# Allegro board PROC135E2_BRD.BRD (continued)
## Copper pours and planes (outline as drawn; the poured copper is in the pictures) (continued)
VCC_3V3_MAIN on TOP: 20.01,71.33 19.23,71.33 19.04,71.53 19.04,72.44 18.88,72.6 18.88,74.98 19.06,75.16 19.42,75.16 20.25,74.33 20.25,71.57
VCC_3V3_MAIN on TOP: 13.95,71.33 14.73,71.33 14.93,71.54 14.93,72.44 15.1,72.6 15.1,74.98 14.91,75.16 14.56,75.16 13.73,74.33 13.73,71.56
VCC_3V3_MAIN on BOTTOM: 20.31,87.96 20.31,85.21 19.06,85.21 19.06,88.04 19.25,88.23 20.04,88.23
VCC_3V3_MAIN on BOTTOM: 10.11,80.53 10.11,78.91 12.25,78.91 12.25,80.53
VCC_3V3_MAIN on BOTTOM: 14.32,76.38 16.13,76.38 16.45,76.06 16.45,74.41 16.29,74.26 15.76,74.26 15.55,74.46 15.55,75.09 15.26,75.39 14.32,75.39
VCC_3V3_MAIN on BOTTOM: 20.31,71.35 20.31,74.38 19.06,74.38 19.06,71.54 19.25,71.35
VCC_3V3_MAIN on BOTTOM: 20.5,84.62 21.52,84.62 22.13,84.01 22.13,79.09 22.4,78.82 22.4,77.3 21.94,76.85 20.53,76.85 20.53,80.63 20.35,80.81 20.35,81.47 20.5,81.62
VCC_3V3_MAIN on BOTTOM: 4.43,61.84 5.07,61.84 5.07,63.44 4.43,63.44
VCC_3V3_MAIN on BOTTOM: 13.66,71.59 13.66,74.38 14.91,74.38 14.91,71.54 14.72,71.35 13.9,71.35
VCC_3V3_MAIN on BOTTOM: 24.19,60.1 24.19,53.88 31.59,53.88 31.59,60.1
VCC_3V3_MAIN on BOTTOM: 13.66,88.23 13.66,85.23 14.91,85.23 14.91,88.04 14.72,88.23
VCC_3V3_MAIN on L06_PWR01: 0.87,88.91 16.94,88.91 16.94,101.45 19.12,103.63 20.18,103.63 21.65,102.16 21.65,101.65 19.26,99.25 19.26,91.91 22,89.17 22,81.29 25.2,78.09 43.69,78.09 43.69,53.47 2.63,53.47 0.87,55.23
VCC_3V3_SYS on TOP: 61.25,49.26 61.25,47.12 61.35,47.02 62.33,47.02 62.45,47.15 62.45,49.23 62.38,49.31 61.3,49.31
VCC_3V3_SYS on TOP: 9.51,134.5 13.53,134.5 13.53,135.77 11.85,135.77 11.53,135.45 9.51,135.45
VCC_3V3_SYS on TOP: 11.38,96.99 11.38,95.67 11.06,95.35 11.06,93.51 11.71,93.51 12.51,94.32 14.5,94.32 14.5,96.99
VCC_3V3_SYS on TOP: 54.86,123.35 55.66,123.35 55.66,122.9 55.98,122.58 57.31,122.58 57.49,122.39 57.49,122.13 57.34,121.97 55.1,121.97 54.86,122.22
VCC_3V3_SYS on TOP: 8.95,101.18 10.14,101.18 10.35,101.38 13.24,101.38 13.24,100.47 8.88,100.47 8.88,101.11
VCC_3V3_SYS on TOP: 9.51,153.09 13.64,153.09 13.64,151.85 11.81,151.85 11.53,152.13 9.51,152.13
VCC_3V3_SYS on TOP: 74.45,153.62 76.71,153.62 76.71,147.82 74.45,147.82
VCC_3V3_SYS on TOP: 47.23,54.89 47.23,58.39 51.74,58.39 51.74,54.89
VCC_3V3_SYS on BOTTOM: 76.46,150.15 77.54,150.15 77.67,150.03 77.67,149.41 77.77,149.31 80.41,149.31 80.46,149.26 80.46,147.33 80.03,146.89 76.62,146.89 76.46,147.06
VCC_3V3_SYS on BOTTOM: 71.22,87.67 71.22,86.07 72.65,86.07 72.65,87.67
VCC_3V3_SYS on BOTTOM: 13.24,63.01 13.24,59.14 15.57,59.14 15.57,63.01
VCC_3V3_SYS on BOTTOM: 16.61,136.41 18.34,136.41 18.47,136.28 18.47,135.5 17.35,134.38 16.79,134.38 16.61,134.56
VCC_3V3_SYS on BOTTOM: 66.65,44.84 66.65,42.61 67.85,42.61 67.85,44.84
VCC_3V3_SYS on BOTTOM: 8.03,110.94 10.67,110.94 10.67,109.71 11.75,109.71 12.59,110.55 12.9,110.55 13.05,110.7 13.05,113.06 13.25,113.26 13.71,113.26 13.81,113.16 13.81,110.57 13.43,110.19 12.79,110.19 11.63,109.02 11.63,107.94 14.3,107.94 14.3,106.77 10.06,106.77 9.1,107.74 9.1,109.46 8.26,110.3 8.03,110.3
VCC_3V3_SYS on BOTTOM: 54.9,122.65 54.9,122.02 57.5,122.02 57.5,122.65
VCC_3V3_SYS on BOTTOM: 58.69,78.76 58.69,77.29 59.66,77.29 59.66,78.76
VCC_3V3_SYS on BOTTOM: 64.83,132.78 65.29,132.78 65.29,132 66.21,132 66.21,131.76 65.58,131.13 65.1,131.13 64.78,131.45 64.78,132.73
VCC_3V3_SYS on BOTTOM: 64.62,84.77 64.62,80.65 63.12,80.65 63.12,83.91 62.13,83.91 62.13,84.7 63.4,84.7 63.47,84.77
VCC_3V3_SYS on L06_PWR01: 9.48,109.67 11.03,109.67 13.03,107.66 13.03,101.03 12.7,100.7 10.57,100.7 8.97,102.3 8.97,109.16
VCC_3V3_SYS on L08_PWR03: 0.64,154.54 84.36,154.54 84.36,5.71 0.64,5.71 ; 8 cut-outs
VCC_5V0 on BOTTOM (solid shape): 19.99,35.62 20.01,35.62 20.03,35.6 20.08,35.51 20.08,35.48 20.07,35.47 20.36,34.98 20.65,35.47 20.64,35.48 20.64,35.51 20.69,35.6 20.71,35.62 20.74,35.62 21.33,35.62 21.37,35.61 21.38,35.57 21.38,32.94 21.39,32.92 21.4,32.9 21.5,32.8 21.5,32.79 21.57,32.69 21.68,32.61 21.71,32.6 21.73,32.59 21.81,32.59 21.85,32.59 22.64,32.59 22.68,32.58 22.69,32.54 22.69,31.28 22.68,31.24 22.64,31.23 18.76,31.23 18.72,31.24 18.71,31.28 18.71,32.96 18.69,32.99 18.66,33.01 16.77,33.01 16.73,33.02 16.72,33.06 16.72,35.57 16.73,35.61 16.77,35.62
VCC_5V0 on TOP: 55.99,119.57 57.52,119.57 57.52,120.22 55.96,120.22 55.36,120.82 54.49,120.82 54.49,118.94 55.36,118.94
VCC_5V0 on TOP: 63.76,66.65 63.76,71.18 65.68,71.18 65.68,66.65
VCC_5V0 on BOTTOM: 7.01,138.24 8.21,138.24 8.21,137.07 7.44,137.07 7.37,137.15 6.5,137.15 6.5,137.71 6.89,137.71 7.01,137.83
VCC_5V0 on BOTTOM: 57.66,147.41 58.72,147.41 58.72,146.45 58.95,146.22 58.95,142.12 57.23,142.12 57.23,144.95 57.66,145.38
VCC_5V0 on BOTTOM: 0.76,116.37 0.76,117.44 3.69,117.44 3.69,116.98 1.98,116.98 1.98,116.37
VCC_5V0 on L06_PWR01: 48,19.55 59.28,30.83 59.28,32.73 68.13,41.58 68.13,71.13 67.41,71.84 51.23,71.84 51.23,62.88 48.47,60.11 48.47,52.67 47.5,51.7 47.5,45.53 45.98,44.01 45.98,38.44 37.42,29.88 22.29,29.88 21.61,30.57 21.61,34.81 20.69,35.72 11.97,35.72 11.97,19.55
VCC_5V0 on L06_PWR01: 7.56,145.75 58.12,145.75 59.38,144.49 59.38,127.12 57.51,125.25 57.51,121.96 58.35,121.12 60.7,121.12 61.19,120.63 61.19,117.01 60.76,116.57 50.76,116.57 50.76,135.09 6.62,135.09 6.02,134.49 5.08,134.49 4.63,134.95 4.63,142.81
VCC_5V0 on L07_PWR02: 0.64,139.08 9.22,139.08 10.87,137.43 10.87,112.99 0.64,112.99
VCC_5V0 on L08_PWR03: 54.92,121.15 65.84,121.15 69.95,117.03 69.95,67.48 68.81,66.33 64.29,66.33 63.81,66.82 63.81,72.35 64.23,72.77 64.23,83.86 63.81,84.28 63.81,89.93 64.23,90.35 64.23,112.9 61.97,115.16 54.92,115.16
VCC_CORE on TOP: 8.8,74.2 10.98,74.2 11.2,73.98 11.2,71.84 11.65,71.39 13.21,71.39 13.62,70.97 13.62,68.59 11.99,68.59 11.48,69.11 7.03,69.11 7.03,72.43
VCC_CORE on TOP: 15.22,94.29 18.66,94.29 19.02,93.93 19.4,93.93 19.41,93.94 21.52,93.94 23.39,92.07 24.05,92.07 24.72,91.4 24.72,85.23 22.77,85.23 22.77,88.15 22.51,88.41 20.47,88.41 20.07,88.81 20.07,90.55 19.56,91.07 14.37,91.07 14,90.69 14,89.02 13.39,88.41 11.75,88.41 11.26,87.92 11.26,85.28 9.61,85.28 9.61,90.96 12.55,93.89 14.82,93.89
VCC_CORE on BOTTOM: 13.57,68.54 13.57,70.96 12.7,71.83 9.61,71.83 9.03,71.25 9.03,69.92 10.41,68.54
VCC_CORE on BOTTOM: 12.55,93.01 16.83,93.01 17.25,93.43 21.47,93.43 22.08,92.82 22.08,91.17 21.77,90.87 21.77,88.53 20.17,88.53 19.92,88.79 19.92,90.54 19.39,91.07 14.2,91.07 14,90.86 14,89.04 13.28,88.33 9.81,88.33 9.81,91.43 10.84,92.46 12,92.46
VCC_CORE on L08_PWR03: 15.41,92.76 18.86,92.76 21.86,89.75 21.86,69.59 19.65,67.37 10.56,67.37 9.93,68 9.93,91.47 10.57,92.12 14.77,92.12
VCC_CSI_IO on TOP: 77.24,150.17 77.24,147.82 78.51,147.82 78.51,152.44 77.24,152.44 77.13,152.33 77.13,150.28
VCC_CSI_IO on BOTTOM: 57.98,152.1 57.98,150.58 61.47,150.58 61.47,152.1
VCC_CSI_IO on L07_PWR02: 50.73,143.19 50.42,143.5 50.42,154.16 78.06,154.16 78.06,143.19
VDD1_LPDDR4_1V8 on BOTTOM: 29.82,79.11 31.35,79.11 31.35,80.52 29.82,80.52
VDD1_LPDDR4_1V8 on L07_PWR02: 47.7,90.54 47.7,76.75 29.84,76.75 29.84,87.21 33.17,90.54
VDD_1V0 on TOP: 54.86,112.4 55.66,112.4 55.66,112.85 55.98,113.17 57.31,113.17 57.49,113.36 57.49,113.62 57.34,113.78 55.1,113.78 54.86,113.53
VDD_1V0 on BOTTOM: 70.08,107.61 70.08,106.13 69.91,105.96 69.45,105.96 69.04,106.36 65.84,106.36 65.84,107.61
VDD_1V0 on BOTTOM: 54.89,113.67 54.89,112.84 57.52,112.84 57.52,113.67
VDD_1V0 on L06_PWR01: 54.66,115.63 61.22,115.63 67.16,109.69 67.16,106.01 66.19,105.04 66.19,100.98 64.37,99.15 64.37,96.48 65.51,95.34 65.51,94.96 64.65,94.1 58.78,94.1 58.78,108.42 54.66,112.54
VDD_1V0 on L07_PWR02: 59.39,99.73 60.73,99.73 60.97,99.49 60.97,94.29 57.4,90.72 56.44,90.72 56.27,90.88 56.27,96.62
VDD_1V2 on BOTTOM: 12.9,123.97 12.9,119.81 14.7,119.81 14.7,123.97
VDD_1V2 on L07_PWR02: 12.62,125.04 23.58,125.04 30.42,118.2 53.49,118.2 60.5,111.2 60.5,110.18 63.3,107.38 63.3,103.98 62.38,103.06 53.39,103.06 52.56,103.9 52.56,106.06 45.72,112.89 14.58,112.89 11.64,115.83 11.64,124.06
VDD_2V5 on TOP: 64.54,97.05 65.92,97.05 65.98,97 65.98,96.41 65.88,96.31 65.21,96.31 65.07,96.17 65.07,94.33 65.24,94.16 65.81,94.16 65.9,94.07 65.9,93.48 65.79,93.38 65.04,93.38 64.54,93.88
VDD_2V5 on TOP: 60.88,123.35 60.08,123.35 60.08,122.9 59.75,122.58 58.43,122.58 58.24,122.4 58.24,122.16 58.43,121.97 60.63,121.97 60.88,122.22
VDD_2V5 on BOTTOM: 58.25,122.55 58.25,121.82 60.85,121.82 60.85,122.55
VDD_2V5 on BOTTOM: 67.11,86.25 65.33,86.25 65.33,87.03 63.83,87.03 63.83,88.25 64.52,88.94 66.27,88.94 67.11,88.1
VDD_2V5 on L06_PWR01: 59.59,126.43 62.87,126.43 73.1,116.19 73.1,101.59 74.09,100.6 74.09,89.27 69.04,84.21 60.15,84.21 58.93,85.43 58.93,88.99 60.76,90.82 62.13,90.82 66.22,94.91 66.22,95.54 65.36,96.41 65.2,96.41 65,96.61 65,98.9 66.91,100.8 66.91,104.74 67.92,105.75 67.92,113.29 62.89,118.32 62.89,120.77 61.93,121.73 58.73,121.73 58.24,122.21 58.24,125.08
VDD_CORE on TOP: 52.81,106.55 54.28,106.55 55.02,105.8 55.02,101.55 53.82,101.55 53.82,105.1 53.44,105.47 52.81,105.47
VDD_CORE on TOP: 15.12,100.3 15.12,94.71 20.3,94.71 20.3,100.3
VDD_CORE on BOTTOM: 23.35,97.09 24.95,97.09 24.95,95.89 21.37,95.89 20.7,96.56 19.02,96.56 18.47,96.01 15.38,96.01 15.38,98.22 15.67,98.51 16.3,98.51 16.63,98.85 16.63,99.99 16.96,100.31 19.36,100.31 20.85,98.82 20.85,98.36 21.99,97.23 23.21,97.23
VDD_CORE on L08_PWR03: 23.8,122.11 53.88,122.11 53.88,117.73 54.37,117.23 54.37,103.99 53.75,103.37 48.24,103.37 47.22,102.35 44.3,102.35 42.99,101.04 37.47,101.04 37.17,100.75 29.9,100.75 28.56,99.4 28.56,95.12 15.26,95.12 11.94,98.44 11.94,110.26
VDD_CORE_REG_SW1 on TOP: 11.64,87.59 13.26,87.59 13.26,85.28 14.38,84.16 14.38,83.45 14.33,83.4 13.21,83.4 11.64,84.98
VDD_CORE_REG_SW2 on TOP: 22.34,87.59 20.71,87.59 20.71,85.28 19.6,84.16 19.6,83.45 19.65,83.4 20.76,83.4 22.34,84.98
VDD_CORE_REG_SW3 on TOP: 11.64,71.99 13.26,71.99 13.26,74.3 14.38,75.42 14.38,76.13 14.33,76.18 13.21,76.18 11.64,74.61
VDD_LPDDR4 on TOP: 28.23,73.52 28.23,69.54 34.49,69.54 34.49,76.47 34.67,76.65 48.51,76.65 50.83,78.96 50.83,90.62 51.77,91.56 51.77,94.15 49.87,96.05 47.53,96.05 46.84,95.37 46.84,94.31 45.4,92.88 34.06,92.88 30.81,96.13 28.24,96.13 27.05,94.95 27.05,80.07 28.93,78.19 28.93,73.52 ; 9 cut-outs
VDD_LPDDR4 on L08_PWR03: 29.62,76.25 52.02,76.25 52.02,96.21 47.65,100.58 37.62,100.58 37.28,100.23 36.66,100.23 35.8,99.37 35.8,98.18 35.39,97.77 29.82,97.77 29.82,92.8 28.58,91.56 28.58,77.29
VDD_MMC1 on TOP: 5.94,99.23 5.94,100.22 6.29,100.57 7.28,100.57 7.28,101.35 4.57,101.35 4.57,99.23
VDD_MMC1_SD on TOP: 3.75,96.96 3.75,98.87 6.21,98.87 6.21,96.96
VDD_MMC1_SD on BOTTOM: 3.84,97.86 5.59,97.86 5.81,98.08 6.18,98.08 6.18,96.94 5.75,96.94 5.63,97.06 3.84,97.06
VDDA1V8 on TOP: 22.63,79.2 23.99,79.2 24.03,79.16 24.03,78.06 22.53,78.06 22.5,78.09 22.5,79.06
VDDA1V8 on TOP: 44.66,73.65 44.66,70.96 42.78,70.96 42.78,73.65
VDDA1V8 on BOTTOM: 42.62,73.47 42.62,71.36 43.56,71.36 43.56,73.47
VDDA1V8 on L08_PWR03: 22.49,79.03 23.93,79.03 24.74,78.22 24.74,75.48 26.67,73.55 43.74,73.55 43.74,70.73 25.45,70.73 22.49,73.69
VDDA_1V8 on TOP: 45.11,73.65 45.11,70.96 46.71,70.96 48.62,72.86 48.62,75.91 47.09,75.91 47.09,74.16 46.59,73.65
VDDA_1V8 on TOP: 60.62,134.14 60.62,132.77 61.71,132.77 61.71,134.14
VDDA_1V8 on BOTTOM: 53.01,100.31 53.01,98.76 54.18,98.76 54.18,100.31
VDDA_1V8 on BOTTOM: 52.01,106.53 51.68,106.86 51.68,112.48 52.88,113.67 52.88,124.9 52.9,124.87 55.14,127.11 57.63,127.11 58.62,128.1 58.62,128.53 58.74,128.66 58.74,131.7 58.72,131.73 59.54,132.55 60.51,132.55 60.88,132.92 60.88,133.23 61.05,133.41 61.87,133.41 61.87,132.54 60.93,131.6 60.52,131.6 59.53,130.61 59.53,126.52 58.84,125.84 57.35,125.84 54.63,123.12 54.63,112.81 55.03,112.4 55.03,107.65 53.92,106.53
VDDA_1V8 on L05_SIG02: 38.23,102.55 38.23,101.56 43.92,101.56 43.92,102.55
VDDA_1V8 on L06_PWR01: 46.46,72.94 46.46,77.6 50.78,81.92 50.78,95.36 45.66,100.48 43.28,100.48 43.28,105.35 41.68,106.95 37.51,106.95 35.28,109.18 35.28,110.73 36,111.45 54.78,111.45 58.16,108.07 58.16,72.94
VDDA_1V8_FB1 on TOP: 51.44,100.34 51.44,98.97 52.63,98.97 52.63,100.34
VDDA_1V8_FB1 on BOTTOM: 51.44,100.39 51.44,98.9 52.61,98.9 52.61,100.39
VDDA_1V8_FB1 on L03_SIG01: 38.01,105.71 40.54,105.71 42.14,104.1 50.74,104.1 51.54,103.3 52.55,103.3 53.09,102.76 53.09,99.26 52.64,98.82 51.48,98.82 49.07,101.22 47.37,101.22 46.93,100.78 38.1,100.78 37.59,101.28 36.63,101.28 36.63,102.26 36.93,102.56 37.28,102.56 37.35,102.64 37.35,105.05
VDDA_1V8_FB2 on BOTTOM: 50.45,106.44 50.71,106.44 50.94,106.21 52.71,106.21 52.71,105.56 50.69,105.56 50.33,105.92 50.33,106.33
VDDA_1V8_FB2 on L07_PWR02: 47.99,106.48 50.74,106.48 51.14,106.08 51.14,104.89 50.25,104 44.73,104 44.73,104.14 45.19,104.6 45.19,105.46 45.47,105.74 47.25,105.74
VDDA_CORE_CSI on TOP: 51.63,104.51 51.63,103.51 53.28,103.51 53.28,104.51
VDDA_CORE_CSI on L07_PWR02: 44.48,103.36 50.53,103.36 51.45,104.27 51.96,104.27 52.14,104.09 52.14,103.09 51.4,102.35 44.87,102.35 44.42,102.8 44.42,103.3
VDDA_CORE_USB on TOP: 51.63,102.58 51.63,101.54 53.32,101.54 53.32,102.58
VDDA_CORE_USB on L08_PWR03: 47.98,102.08 48.54,102.64 52.53,102.64 52.53,100.19 48.64,100.19 47.98,100.85
VDDA_DDR_PLL0 on BOTTOM: 24.46,99.25 25.45,99.25 25.45,98.69 25.94,98.21 25.94,97.6 23.98,97.6 23.88,97.7 23.88,98.67
VDDA_DDR_PLL0 on L07_PWR02: 29.71,99.35 29.71,98.39 37.73,98.39 37.96,98.62 37.96,99.35
VDDA_LM5141 on BOTTOM: 30.43,44.93 31.74,44.93 31.81,45 32.69,45 32.69,44.22 31.07,44.22 31.07,43.76 30.96,43.66 30.57,43.66 30.43,43.8
VDDA_LM5141 on L07_PWR02: 30.43,46.78 30.43,42.62 36.12,42.62 36.12,46.78
VDDC_1V2 on L07_PWR02: 50.43,14.5 50.68,14.26 53.16,14.26 53.16,17.29 56.39,20.51 59.82,20.51 59.82,23.17 55.17,23.17 50.43,18.44
VDDR_CORE on TOP: 23.33,95.27 23.33,93.96 23.17,93.8 22.67,93.8 22.67,93.31 23.57,92.41 24.77,92.41 24.77,95.27
VDDR_CORE on BOTTOM: 22.53,94.41 22.53,91.1 22.1,90.67 22.1,88.66 24.87,88.66 24.87,94.41
VDDR_CORE on L06_PWR01: 37.32,106.49 41.42,106.49 42.78,105.14 42.78,100.38 36.98,100.38 35.72,101.63 29.23,101.63 28.86,101.26 26.84,101.26 23.88,98.3 23.88,93.13 23.29,92.55 19.94,92.55 19.94,99.05 26.64,105.75 36.58,105.75
(no net) on TOP: 19.85,33.11 20.93,33.11 21.82,32.22 22.85,32.22 22.85,31.28 22.56,31 17.4,31 17.4,35.66 19.95,35.66 20.61,35 20.61,34.38 20.49,34.25 19.95,34.25 19.85,34.15
(no net) on TOP: 14.48,49.41 16.36,49.41 16.36,47.59 15.54,47.59 15.03,48.11 14.48,48.11
(no net) on TOP: 8.31,43.61 7.43,43.61 7.35,43.68 7.35,43.98 7.24,44.09 6.92,44.09 6.83,44 6.83,43.85 5.91,43.85 5.91,43.55 6.83,43.55 6.83,43.28 6.93,43.18 7.23,43.18 7.34,43.29 8.31,43.29
(no net) on TOP: 5.87,31.36 6.77,31.36 6.83,31.41 6.83,31.81 6.97,31.96 7.21,31.96 7.35,31.81 7.35,31.6 8.27,31.6 8.27,31.3 7.35,31.3 7.35,31.16 7.23,31.04 5.87,31.04
(no net) on TOP: 24.15,32.32 24.15,26.49 26.04,26.49 26.04,29.93 24.8,31.17 24.8,32.32
(no net) on TOP: 21.85,29.93 21.85,26.48 23.75,26.48 23.75,32.32 23.12,32.32 23.12,31.2
(no net) on TOP: 5.87,46.36 6.75,46.36 6.83,46.43 6.83,46.73 6.94,46.84 7.26,46.84 7.35,46.75 7.35,46.6 8.27,46.6 8.27,46.3 7.35,46.3 7.35,46.03 7.25,45.93 6.95,45.93 6.84,46.04 5.87,46.04
(no net) on TOP: 13.64,43.89 16.24,43.89 16.24,42.97 13.64,42.97
(no net) on TOP: 14.01,42.67 16.35,42.67 16.35,40.38 15.56,40.38 15.14,39.96 14.01,39.96
(no net) on TOP: 8.31,28.61 7.43,28.61 7.35,28.68 7.35,28.98 7.24,29.09 6.92,29.09 6.83,29 6.83,28.85 5.91,28.85 5.91,28.55 6.83,28.55 6.83,28.28 6.93,28.18 7.23,28.18 7.34,28.29 8.31,28.29
(no net) on TOP: 24.98,32.23 24.98,31.53 26.2,30.31 29.99,30.31 29.99,33.72 27.9,33.72 27.9,32.3 26.12,32.3 26.04,32.23
(no net) on BOTTOM: 16.26,50.18 16.26,49.36 16.59,49.02 16.59,48.79 16.96,48.42 17.36,48.42 17.36,47.23 16.56,47.23 16.25,47.54 14.57,47.54 14.57,48.27 14.25,48.59 14.25,50.04 14.39,50.18
(no net) on BOTTOM: 16.48,43.23 17.39,43.23 17.39,43.95 14.47,43.95 14.06,43.55 14.06,41.08 15.08,41.08 15.08,42.66 15.38,42.96 16.2,42.96
(no net) on BOTTOM: 16.96,49.39 17.62,49.39 17.9,49.11 17.9,48.14 18.02,48.02 19.22,48.02 19.22,48.85 19.5,48.85 19.5,45.37 17.77,45.37 17.62,45.53 17.62,47.94 17.51,48.04 17.51,48.55 17.44,48.63 16.96,48.63
(no net) on BOTTOM: 63.56,104.68 65.08,104.68 65.34,104.42 65.34,103.99 65.21,103.86 62.63,103.86 62.31,104.18 62.31,105.27 63.4,105.27 63.4,104.84
(no net) on BOTTOM: 5.11,46.74 9.04,46.74 9.04,46.05 8.56,46.05 8.56,43.7 8.94,43.7 8.94,43.03 5.11,43.03
(no net) on BOTTOM: 26.58,33.69 26.58,30.32 29.95,30.32 29.95,33.69
(no net) on BOTTOM: 16.59,43.08 17.41,43.08 17.41,42.38 17.14,42.11 16.9,42.11 16.37,41.57 16.37,40.98 16.24,40.86 15.5,40.86 15.39,40.96 15.39,42.53 15.56,42.7 16.21,42.7
(no net) on BOTTOM: 67.36,103.37 67.31,103.42 67.31,103.86 67.21,103.96 66,103.96 65.83,104.14 65.83,104.42 66,104.59 68.16,104.59 68.53,104.96 69.43,104.96 69.43,105.26 69.61,105.44 69.89,105.44 70.06,105.26 70.06,103.37
(no net) on BOTTOM: 16.96,40.95 17.62,40.95 17.95,41.28 17.95,42.32 19.17,42.32 19.22,42.28 19.22,41.44 19.5,41.44 19.5,44.96 17.77,44.96 17.62,44.81 17.62,42.23 17.51,42.13 17.51,41.79 17.44,41.71 16.96,41.71
(no net) on BOTTOM: 11.48,29.63 11.19,29.92 11.19,32.82 11.55,33.18 12.12,33.18 13.65,34.71 13.65,38.57 15.08,40 15.08,43.08 14.61,43.55 14.06,43.55 14.06,40.84 11.83,38.61 11.83,35.99 11.14,35.29 9.42,35.29 8.96,34.83 8.96,33.86 8.26,33.16 5.2,33.16 5.2,28.05 6.33,26.92 11.52,26.92 12,26.45 17.19,26.45 17.5,26.76 17.5,29.38 15.33,29.38 15.07,29.63
(no net) on BOTTOM: outline of 97 points within 0.63,5.71 84.36,154.54 ; 85 cut-outs
(no net) on BOTTOM: 22.69,32.59 22.69,31.23 18.71,31.23 18.71,33.01 16.72,33.01 16.72,35.62 21.38,35.62 21.38,32.92 21.71,32.59
(no net) on L03_SIG01: outline of 96 points within 0.63,5.71 84.36,154.54 ; 116 cut-outs
(no net) on L05_SIG02: outline of 96 points within 0.63,5.71 84.36,154.54 ; 214 cut-outs
(no net) on L07_PWR02: 18.54,47 15.69,47 15,46.3 15,45.16 12.12,42.29 4.67,42.29 4.67,48 8.08,48 9.38,49.29 9.38,52.02 10.4,53.04 17.99,53.04 18.54,52.48
(no net) on L10_SIG03: outline of 96 points within 0.63,5.71 84.36,154.54 ; 177 cut-outs
CAN_IO_3V3 on BOTTOM: 4.43,66.21 5.07,66.21 5.07,63.82 4.43,63.82
CAN_IO_3V3 on L07_PWR02: 0.94,67.2 4.01,67.2 4.01,67.16 19.83,67.16 21.08,65.91 21.08,61.41 23.85,58.64 25.22,58.64 29.7,54.17 29.7,41.71 31.63,39.78 31.63,25.54 33.89,23.28 33.89,18 32.9,17.01 26.19,17.01 26.19,18.68 28.78,18.68 30.01,19.91 30.01,23.34 26.6,26.76 26.6,51.27 23.52,54.34 0.94,54.34
CPSW1_GPIO_0 on BOTTOM: 81.95,84.9 81.95,82.3 82.43,82.3 82.43,81.47 83.22,81.47 83.22,84.9
CPSW1_LED_1000 on BOTTOM: 82.38,106.99 82.38,104.42 83.65,104.42 83.65,106.99
CPSW1_LED_ACT on BOTTOM: 79.29,84.93 79.29,82.32 79.76,82.32 79.76,81.49 80.56,81.49 80.56,84.93
CS_LM5141 on BOTTOM: 32.23,58.04 32.23,53.86 42.98,53.86 42.98,58.68 34.44,58.68 33.8,58.04
DRAIN1 on BOTTOM (solid shape): 17.59,49.39 17.61,49.38 17.63,49.37 17.88,49.12 17.89,49.11 17.9,49.09 17.9,48.16 17.9,48.14 17.92,48.11 17.93,48.09 17.93,48.05 17.94,48.01 17.98,48 19.18,48 19.22,48.01 19.23,48.05 19.23,48.4 19.25,48.46 19.25,48.51 19.25,48.8 19.27,48.84 19.3,48.85 19.44,48.85 19.47,48.84 19.49,48.8 19.49,48.59 19.48,48.55 19.47,48.51 19.47,47.85 19.48,47.79 19.5,47.74 19.5,45.43 19.48,45.39 19.44,45.37 17.79,45.37 17.77,45.38 17.75,45.39 17.63,45.51 17.62,45.53 17.62,45.55 17.62,47.92 17.61,47.94 17.59,47.98 17.59,48.04 17.57,48.07 17.57,48.08 17.57,48.58 17.55,48.61 17.51,48.63 17.07,48.63 17.05,48.63 17.03,48.64 16.97,48.7 16.96,48.72 16.96,48.74 16.96,49.34 16.97,49.37 17.01,49.39
DRAIN1 on L08_PWR03: 17.57,47.95 17.57,45.48 19.38,45.48 19.38,47.95
DRAIN2 on BOTTOM (solid shape): 19.44,44.96 19.48,44.95 19.5,44.91 19.5,42.63 19.49,42.61 19.47,42.59 19.47,41.81 19.48,41.76 19.49,41.72 19.49,41.49 19.47,41.45 19.44,41.44 19.29,41.44 19.25,41.45 19.23,41.49 19.23,42.26 19.22,42.3 19.17,42.32 17.95,42.32 17.95,42.31 17.93,42.29 17.93,41.28 17.92,41.26 17.91,41.24 17.63,40.96 17.61,40.95 17.59,40.95 17.01,40.95 16.97,40.96 16.96,41 16.96,41.66 16.97,41.69 17.01,41.71 17.42,41.71 17.44,41.71 17.45,41.72 17.5,41.77 17.51,41.79 17.51,41.81 17.51,42.1 17.52,42.12 17.53,42.14 17.6,42.21 17.61,42.23 17.62,42.25 17.62,42.3 17.62,43.28 17.62,43.28 17.62,44.79 17.62,44.81 17.63,44.82 17.75,44.95 17.77,44.96 17.79,44.96
DRAIN2 on L08_PWR03: 17.57,44.85 17.57,42.44 19.38,42.44 19.38,44.85
ETH1_EARTH on TOP: 74.91,100.93 74.91,88.23 74.27,87.59 74.27,83.15 77.15,83.15 77.15,85.4 84.29,85.4 84.29,103.95 74.27,103.95 74.27,101.56
ETH1_EARTH on BOTTOM: 74.91,100.93 74.91,88.23 74.27,87.59 74.27,83.15 77.15,83.15 77.15,85.4 84.29,85.4 84.29,103.95 74.27,103.95 74.27,101.56 ; 2 cut-outs
ETH1_EARTH on L02_GND01, L03_SIG01, L04_GND02, L05_SIG02, L06_PWR01, L07_PWR02, L08_PWR03, L09_GND03, L10_SIG03, L11_GND04: 74.91,100.93 74.91,88.23 74.27,87.59 74.27,83.15 77.15,83.15 77.15,85.4 84.29,85.4 84.29,103.95 74.27,103.95 74.27,101.56
FT4232_USB_VBUS on TOP: 9.28,17.84 4.97,17.84 4.97,18.53 5.69,19.25 9.28,19.25
FT4232_USB_VBUS on BOTTOM: 9.23,11.44 9.74,11.44 9.74,10.55 9.76,10.54 9.76,8.99 9.72,8.95 7.94,8.95 7.71,9.18 7.71,13.85 7.41,14.16 7.41,17.36 7,17.76 7,18.49 7.7,19.19 9.26,19.19 9.61,18.83 9.61,17.92 9.23,17.54
HDMI_EARTH on TOP: 0.64,125.13 7.75,125.13 8.44,124.45 8.44,122.95 7.72,122.24 4.22,122.24 3.18,121.2 3.18,110.83 4.35,109.67 7.95,109.67 8.41,109.21 8.41,107.43 7.77,106.8 3.36,106.8 3.15,106.59 3.15,105.75 2.95,105.55 0.89,105.55 0.64,105.8
HDMI_EARTH on L02_GND01: 0.64,125.13 7.75,125.13 8.44,124.45 8.44,122.95 7.72,122.24 4.22,122.24 3.18,121.2 3.18,110.83 4.35,109.67 7.95,109.67 8.41,109.21 8.41,107.43 7.77,106.8 3.36,106.8 3.15,106.59 3.15,105.75 2.95,105.55 0.89,105.55 0.64,105.81
LDO_3V3 on L07_PWR02: 20.04,51.49 25.04,51.49 26,50.53 26,48.16 22.67,44.83 15.64,44.83 15.64,46.33 18.53,46.33 19.63,47.43 19.63,51.08
SOC_DVDD1V8 on TOP: 2.99,89.19 5.73,89.19 5.73,86.5 2.71,86.5 2.71,88.91
SOC_DVDD1V8 on BOTTOM: 28.12,78.7 31.45,78.7 31.45,76.98 28.12,76.98
SOC_DVDD1V8 on L07_PWR02: 0.65,109.55 3.3,112.21 39.22,112.21 39.22,107.51 38.43,107.51 38.1,107.18 38.1,106.82 37.95,106.67 37.7,106.67 37.21,107.15 35.74,107.15 34.88,106.29 34.88,104.37 14.7,104.37 11.6,101.27 11.6,94.22 39.02,94.22 43.03,98.24 43.03,100.32 43.61,100.9 44.76,100.9 44.76,99.89 45.65,98.99 45.65,94.96 41.87,91.17 32.84,91.17 29.09,87.42 27.97,87.42 27.7,87.14 27.7,83.29 28.87,82.11 28.87,75.71 24.37,75.71 23.01,77.07 23.01,81.06 22.1,81.97 11.62,81.97 8.64,84.95 4.6,84.95 0.65,88.9
SOC_DVDD3V3 on TOP: 11.82,100.16 11.82,97.5 14.66,97.5 14.66,100.16
SOC_DVDD3V3 on L07_PWR02: 35.49,106.31 37.34,106.31 37.47,106.19 37.98,106.19 38.43,106.64 38.43,106.85 38.59,107 39.56,107 40.08,107.52 44.29,107.52 44.76,107.05 44.76,105.38 43.55,104.16 43.55,103.12 44.51,102.15 44.51,101.51 43.63,101.51 42.39,100.27 42.39,98.69 38.89,95.19 12.11,95.19 12.11,101.19 14.59,103.68 35.31,103.68 35.31,106.13
SOC_USB0_VBUS on L07_PWR02: 51.01,76.54 51.01,88.89 53.49,91.38 53.49,97.14 49.25,101.39 48.01,101.39 47.73,101.11 47.73,99.84 51.21,96.36 51.21,91.43 48.97,89.19 48.97,76.54
SOC_VDDSHV5_SDIO on L06_PWR01: 34.92,108.93 23.32,108.93 22.71,108.32 22.71,106.72 23.04,106.39 36.27,106.39 36.5,106.62 36.5,107.35
SW_LM5141 on TOP: 45.49,53.45 45.49,44.66 40.87,44.66 40.87,51.14 42.15,51.14 42.15,53.45
SW_LM5141 on BOTTOM: 35.36,53.44 35.36,49.75 35.17,49.56 35.17,48.67 35.46,48.38 36.21,48.38 36.72,48.89 40.66,48.89 40.66,47.19 45.5,47.19 45.5,53.44
UART_SHIELD on TOP, BOTTOM, L02_GND01, L03_SIG01, L04_GND02, L05_SIG02, L06_PWR01, L07_PWR02, L08_PWR03, L09_GND03, L10_SIG03, L11_GND04: 0.64,23.32 6.83,23.32 6.83,20.18 6.53,19.88 4.07,19.88 3.65,19.45 3.65,14.15 4.16,13.63 6.48,13.63 6.86,13.25 6.86,11.66 0.64,11.66
USB_TYPEA_EARTH on TOP, BOTTOM, L02_GND01, L03_SIG01, L04_GND02, L05_SIG02, L06_PWR01, L07_PWR02, L08_PWR03, L09_GND03, L10_SIG03, L11_GND04: 72.62,79.66 72.62,77.31 76.81,77.31 77.61,76.51 77.61,68.02 76.86,67.27 72.62,67.27 72.62,64.99 84.36,64.99 84.36,79.66
USB_TYPEC1_EARTH on TOP, BOTTOM, L02_GND01, L03_SIG01, L04_GND02, L05_SIG02, L06_PWR01, L07_PWR02, L08_PWR03, L09_GND03, L10_SIG03, L11_GND04: 0.64,39.11 0.64,52.35 8.23,52.35 8.23,49.05 7.98,48.79 4.27,48.79 3.77,48.29 3.77,41.58 4.23,41.13 7.94,41.13 8.23,40.83 8.23,39.11
USB_TYPEC2_EARTH on TOP, BOTTOM, L02_GND01, L03_SIG01, L04_GND02, L05_SIG02, L06_PWR01, L07_PWR02, L08_PWR03, L09_GND03, L10_SIG03, L11_GND04: 0.64,24.11 0.64,37.35 8.23,37.35 8.23,34.05 7.98,33.79 4.27,33.79 3.77,33.29 3.77,26.58 4.23,26.13 7.94,26.13 8.23,25.83 8.23,24.11
VHDMI_AVCC_1V2 on BOTTOM: 13.24,119.11 15.36,119.11 15.36,115.53 14.53,115.53 14.15,115.91 14.15,117.16 13.24,118.07
VHDMI_CVCC_1V2 on BOTTOM: 15.46,124.05 15.46,122.55 17.04,122.55 17.04,124.05
VHDMI_CVCC_1V2 on L06_PWR01: 16.59,123.94 18.21,123.94 19.85,122.3 19.85,120.73 20.14,120.44 21.64,120.44 22.02,120.82 22.02,122.21 23.95,122.21 25.05,121.12 25.05,112.89 23.14,110.98 18.24,110.98 17.99,111.24 17.99,116.02 16.36,117.64 16.36,123.71
VHDMI_IOVCC_3V3 on BOTTOM: 13.19,110.04 13.19,108.55 14.71,108.55 14.71,110.04
VHDMI_IOVCC_3V3 on L06_PWR01: 14.28,126.38 24.59,126.38 28.3,122.67 28.3,114.19 27.33,113.22 25.71,113.22 25.71,121.65 24.69,122.67 21.06,122.67 21.06,121.07 20.88,120.89 20.63,120.89 20.5,121.02 20.5,122.34 18.44,124.4 16.23,124.4 15.32,123.48 15.32,117.87 17.43,115.76 17.43,109.56 12.63,109.56 12.14,110.05 12.14,124.25
VMAIN on BOTTOM (solid shape): 29.9,33.69 29.93,33.68 29.94,33.66 29.95,33.63 29.95,30.37 29.94,30.34 29.93,30.33 29.9,30.32 26.63,30.32 26.6,30.33 26.59,30.34 26.58,30.37 26.58,33.21 27.21,33.21 27.21,33.16 27.21,33.11 27.23,33.06 27.25,33.01 27.28,32.97 27.32,32.93 27.36,32.9 27.41,32.88 27.46,32.86 27.51,32.86 27.56,32.86 27.61,32.86 27.66,32.88 27.71,32.9 27.75,32.93 27.79,32.97 27.82,33.01 27.84,33.06 27.86,33.11 27.87,33.16 27.87,33.21 27.86,33.26 27.84,33.31 27.82,33.36 27.79,33.4 27.75,33.44 27.71,33.47 27.66,33.49 27.61,33.51 27.56,33.52 27.51,33.52 27.46,33.51 27.41,33.49 27.36,33.47 27.32,33.44 27.28,33.4 27.25,33.36 27.23,33.31 27.21,33.26 27.21,33.21 26.58,33.21 26.58,33.63 26.59,33.66 26.6,33.68 26.63,33.69
VMAIN on TOP: 13.84,47.76 14.86,47.76 15.32,47.29 16.27,47.29 16.39,47.17 16.39,46.6 16.19,46.4 14.96,46.4 14.81,46.55 13.84,46.55
VMAIN on TOP: 32.01,40.12 32.01,52.39 40.46,52.39 40.46,40.12
VMAIN on BOTTOM: 46.11,10.63 46.47,10.63 46.47,9.66 46.85,9.28 46.85,7.33 46.55,7.02 44.49,7.02 44.49,7.96 45.81,7.96 45.81,9.36 46.11,9.66
VMAIN on BOTTOM: 14.95,47.33 14.95,46.39 17.36,46.39 17.36,47.08 16.43,47.08 16.18,47.33
VMAIN on L06_PWR01: 9.35,52.52 9.35,36.69 21.4,36.69 22.9,35.19 22.9,31.03 33.52,31.03 36.3,33.81 39.43,33.81 41.74,36.12 41.74,52.52
VMAIN on L08_PWR03: 44.21,6.1 43.31,7 43.31,10.25 42.01,11.55 27.1,11.55 24.06,14.59 24.06,34.7 29.15,34.7 30.38,33.47 30.38,26.89 29.44,25.95 29.44,17.87 32.41,14.9 46.64,14.9 47.75,13.78 47.75,6.72 47.13,6.1
VPP_1V8 on TOP: 22.8,82.61 24.09,82.61 24.09,81.45 23.97,81.32 21.9,81.32 21.9,81.71
VPP_1V8 on L06_PWR01: 25.61,95.13 25.61,90.64 25.35,90.39 25.35,82.79 24.21,81.65 22.49,81.65 22.49,82.47 23.12,83.1 23.12,91.5 24.39,92.77 24.39,97.97 27.18,100.76 29.22,100.76 29.22,99.33 27.66,99.33 26.26,97.93 26.26,95.79
VPP_1V8 on L08_PWR03: 29.03,99.9 35.13,99.9 35.28,99.76 35.28,98.62 35.01,98.35 29.11,98.35 28.76,98.71 28.76,99.64
XDS_SHIELD on TOP, BOTTOM, L02_GND01, L03_SIG01, L04_GND02, L05_SIG02, L06_PWR01, L07_PWR02, L08_PWR03, L09_GND03, L10_SIG03, L11_GND04: 77.07,12.23 77.07,9.87 78.27,9.87 80,11.59 84.36,11.59 84.36,22.57 78.08,22.57 78.08,19.77 80.27,19.77 81.09,18.96 81.09,13.95 80.89,13.75 78.59,13.75
XDS_USB_VBUS on TOP: 75.29,15.69 79.99,15.69 79.99,15.03 79.35,14.39 76.37,14.39 76.06,14.08 75.29,14.08
XDS_USB_VBUS on BOTTOM: 73.84,17.44 73.84,24.09 75.22,24.09 75.22,22.76 75.44,22.76 75.44,21.27 78.73,17.99 78.73,14.78 78,14.05 74.78,14.05 74.78,16.5
XDS_USB_VBUS on L08_PWR03: 57.16,26.65 57.16,25.59 58.33,24.42 73.19,24.42 73.7,23.91 73.7,10.17 72.65,9.12 48.72,9.12 48.72,6.21 76.25,6.21 78.03,7.99 78.03,21.08 79.92,22.97 79.92,26.2 79.46,26.65
N17133547 on BOTTOM: 71.22,90.82 71.22,88.05 72.75,88.05 72.75,90.82
N17153383 on TOP: 25.05,89.32 26.27,89.32 26.27,85.84 25.05,85.84
N17153383 on BOTTOM: 22.1,88.25 24.77,88.25 24.77,86.93 25.61,86.93 25.61,85.99 25.43,85.81 25.2,85.81 24.67,85.28 23.6,85.28 23.6,86.37 23.19,86.78 22.1,86.78
N17253632 on TOP: 48.23,15.52 48.23,11.92 51.12,11.92 51.12,13.62 50.39,14.36 50.39,15.52
N17253632 on BOTTOM: 48.12,16.04 48.12,13.5 47.36,12.74 46.64,12.74 46.64,12.01 47.32,12.01 47.49,11.85 50.97,11.85 50.97,13.4 50.13,13.4 49.8,13.73 49.8,16.04
N17253649 on BOTTOM: 46,16.03 47.38,16.03 47.38,13.5 46.98,13.09 46.51,13.09 46.43,13.01 46.15,13.01 46.15,13.08 46,13.23
N17726648 on TOP: 51.01,70.04 51.01,69.41 54.23,69.41 54.23,70.04
N17849698 on BOTTOM: 14.24,32.11 15.53,32.11 15.7,31.94 15.7,29.68 18.23,29.68 18.23,32.67 18.21,32.7 14.24,32.7
N17850096 on BOTTOM: 15.17,34.46 15.17,35.37 16.44,35.37 16.44,33.11 16.32,33 14.21,33 14.21,33.5
N17936309 on BOTTOM: 15.28,36.14 15.28,35.68 16.36,35.68 16.36,38.77 15.37,38.77 15.37,36.23
N22685527 on TOP: 54.71,51.71 54.71,50.8 54.78,50.73 57.62,50.73 57.63,50.74 57.7,50.67 57.7,50.34 57.75,50.3 58.98,50.3 59.05,50.36 59.05,51.68 58.99,51.74 54.74,51.74
N22685551 on BOTTOM: 17.48,109.72 17.48,108.07 15.01,108.07 15.01,109.72

Small or netless copper shapes (teardrops, artwork), in the pictures only: 1717 on TOP, 1424 on BOTTOM, 391 on L03_SIG01, 487 on L05_SIG02, 3 on L06_PWR01, 14 on L07_PWR02, 6 on L08_PWR03, 402 on L10_SIG03

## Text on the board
Ref Des/Assembly Bottom: PROC135E2 ASSEMBLY BOTTOM
Ref Des/Silkscreen Bottom: AUTOMATION CONN | uSD | MMC2 CONN | DGND | CSI FLEX CONN | NOT FCC APPROVED FOR RESALE | FOR EVALUATION ONLY; | ASSY#
User.Comments: CR_1_21 | CR_11_1 | CR_UQFN16_TMUX1574_70X100_0-6_TOP_1 | CR_UQFN16_TMUX1574_70X100_0-6_TOP_2 | CR_INA_BGA_6 | CR_UNNAMED_1 | CR_ETH_114E1_1 | CR_3_2 | CR_1_9 | BOARD NAME: | AM62A EVM  BOARD | REV: E2 | DATE: 28/09/22 | DESCRIPTION: | SHEET | OF | 19 | PROC135E2 | SCALE: 1 | TEXAS INSTRUMENTS
Ref Des/Assembly Top: PROC135E2 ASSEMBLY TOP
Ref Des/Silkscreen Top: CAN RST | DGND | 1V8 | TYPE-C:2 | PMIC | PRG | TYPE-C:1 | FTDI LED | SoC LED | VCC_CORE | 5V0 | PGOOD | 3V3 | MAIN | 0V85 | RST | B7 | VCC1V1 | ERRORn | B0 | B15 | VDDA | XDS110 | 3V3_SYS | MCU_PORz | ETH_CLK_OUT | B8 | EXP LED | WDOG_DIS | PORz | RSTz | REFCLK | 1V0 | 3V3_TA | XDS | USB | 3V3_XDS | L_R+ | L_L+ | M.2 Key-E | 1V2 | SDIO | VPP | SoC INTn | 2V5 | I2C1_SCL | I2C1_SDA | TYPE-C | UART | PWR | DRP | FTDI | MCU HDR | USER EXPN | BOOTMODE | LPDDR4 | 110 | MIPI CSI-2 | TYPE-A CONN | MIC.HPHONE | RGMII-1 | JTAG | HDMI | VMAIN | JTAG CTI | eMMC | RGMII-2 | CONN | OPN# | SK-AM62A-LP | AM62A SKEVM | PROC135E2 | SL#
PAGE_OUTLINE: LAYOUT BY | REVIEWED BY | APPROVED BY | SIGNATURES | AMB | SK | ZA | 280922 | DATE | SCALE: | SIZE | D | NONE | TEXAS INSTRUMENTS | AM62A  EVM  BOARD | SHEET 1 OF 19 | PROC135E2 | Rev | E2
DIMENSION: 18. | 16. | 17. | 1. | 11. | 12. | 13. | 14. | 15. | 8. | 10 | 2. | 3. | 4. | 6. | 7. | 5. | 9. | IMPEDANCE MISTRAL SHALL APPROVE THE MODIFIED WIDTHS AND SPACING. | FOR STACKUP DETAIL PROC135E1_STACKUP.PDF SHALL BE REFERRED. | FABRICATE PCB IN ACCORDANCE WITH IPC-6012D, CLASS 2; PER IPC-6011.  PCB SHALL BE MANUFACTURED USING  ITEQ IT 180A OR EQUIVALENT | TRACE WIDTH SHALL BE MEASURED ON THE SURFACE IN CONTACT WITH THE LAMINATE. | TEST REQUIREMENTS: | THIEVING IS ALLOWED ONLY IN THE PANEL FRAME, NOT IN THE CIRCUIT AREA. | TEAR DROPS SHALL BE ADDED ON VIA'S AND THROUGH HOLE PADS IN ALL INTERNAL AND OUTER LAYERS. | ENSURE UL REGISTERED E-FILE NUMBER SHALL BE PRINTED ON THE PCB SILKSCREEN. | VIA ON PAD SHALL BE RESIN FILLED AND CAP-PLATED. | ALL HOLES SHALL BE LOCATED WITHIN 0.15MM  DIAMETER OF TRUE POSITION. | LAYER TO LAYER REGISTRATION SHALL BE WITHIN 0.125MM. | CONDUCTOR WIDTH SHALL NOT BE LESS THAN 20% FROM ITS ORIGINAL DATA. INCASE FOR MATCHING | BOARD FINISHED SHALL BE ACCORDING TO IPC-6012D CLASS 2. | AUTOMATED OPTICAL INSPECTION OF ALL THE LAYERS IS REQUIRED. | FINISH: | ALL UNCONNECTED VIA'S SHALL BE SUPPRESSED IF REQUIRED. | FINISHED PCB THICKNESS SHALL BE 0.049" +/-10%. | MATERIALS: | BOW AND TWIST SHALL NOT EXCEED MORE THAN 0.75% OF THE DESIGN LENGTH. | MARKING: | MIN TRACE WIDTH/SPACING ON BOARD IS 0.0032"/0.0033". | IF THE SILK SCREEN FALLS ON SOLDERABLE AREAS. | THICKNESS SHALL BE 0.04-0.06 MICRONS OF SOLDERABLE IMMERSION GOLD SURFACE. | 100% NET LIST ELECTRICAL VERIFICATION USING MISTRAL SUPPLIED IPC-D-356 NET LIST FOR OPENS AND SHORTS. | LAMINATE AND PREPREG (B-STAGE) TO BE IN ACCORDANCE WITH IPC-4101/126. | (MIN.TG 170) | THAT ARE 0.08(0.003") PER SIDE SHALL BE REDUCED IF REQUIRED. | SURFACE AND VIA HOLES FINISH SHALL NOT BE LESS THAN 20UM [0.00079"], INCASE OF LASER | ALL HOLES SURROUNDED BY LAND <=0.010" SHALL BE COMPLIANCE TO IPC6012, CLASS 2. | COPPER FOIL TO BE IN ACCORDANCE WITH IPC-MF-150. UNLESS OTHERWISE SPECIFIED, | ALL EXPOSED CONDUCTIVE PATTERN AREAS NOT COVERED WITH SOLDER MASK OR OTHER PLATING SHALL BE ENIG, | ELECTROLESS NICKEL/IMMERSION GOLD, ELECTROLESS NICKEL SHALL BE 3-6 MICRONS, TYPICAL IMMERSION GOLD | APPLY LIQUID PHOTO IMAGEABLE SOLDER MASK PER IPC-SM-840, CLASS H, TO BOTH SIDES OF THE BOARD OVER BARE COPPER. | VIA HOLES SHALL BE RESIN FILLED AND COVERED WITH SOLDER MASK. ONLY SOLDER MASK IMAGES | ALL OTHER SOLDER MASK IMAGES SHALL NOT BE ENLARGED. DEFAULT COLOUR OF SOLDER MASK SHALL BE BLUE. | SILKSCREEN SHALL BE WHITE, PERMANENT, ORGANIC, NON-CONDUCTIVE INK. THERE SHALL BE | VIA'S, BLIND VIA'S SHALL NOT BE LESS THAN 12UM [0.00047"] AND BURIED VIA'S SHALL NOT BE LESS THAN 15UM [0.0006"]. | BOARD SHALL MEET THE REQUIREMENTS OF UL-796E WITH FLAMMABILITY RATING OF MINIMUM 94V-0. UL LOGO, | NO SILKSCREEN ON ANY SOLDERABLE COMPONENT PAD. CLIPPING OF SILK SCREEN SHALL BE ALLOWED | MANUFACTURER'S IDENTIFICATION AND DATE CODE LETTER SHALL BE RENDERED IN SILKSCREEN. | THE COPPER FOIL THICKNESS TOLERANCES SHALL BE AS PER IPC 6012B TABLE NO.3-7 AND 3-8. | DETAIL-A | FABRICATION NOTES:
DEVICE_TYPE_TOP: 32.725 | BACKING PLATE OUTLINE | NON-PLATED MOUNTING HOLE | 30.225 | SOCKET OUTLINE | 4X | dia | 1.70 | 13.8625 | 8.7825 | 8.0000 | 0 | 0.80 | TYP | 441X | 0.42 | MIN  PADS | 11.3225 | NON-PLATED ALIGNMENT HOLE | 2X | 0.850
User.14: A | TASY PROC100E2_BRD
User.15: A | TASY PROC100E2_BRD
User.17: P/N AM62A LPDDR4 FAB REV 1 | LAYER 1
User.18: AM62A LPDDR4 FAB REV 1 | P/N AM62A LPDDR4 FAB REV 1 | LAYER 12
User.20: WHEN ACTUATOR IS OPENED | CARD PUSH OUT | CARD PUSH LOCK | CARD PUSH IN | PROCxxxE1 ASSEMBLY BOTTOM REV A
User.22: B | c | D | A
User.23: N | E | G | K | H | F | P | M
User.45: B | c | D | A | N | E | G | K | H | F | P | M | FIGURE | SIZE | 7.99 | 8.0 | 36.0 | 40.0 | 44.0 | 52.0 | 66.0 | 118.0 | 32.0 | 34.0 | 48.0 | 62.0 | 68.0 | 108.0 | 126.0 | 48.0x22.0 | 62.0x24.0 | 68.0x34.0 | 82.0x24.0 | 118.0x28.0 | DRILL CHART: TOP to BOTTOM | ALL UNITS ARE IN MILS | TOLERANCE | +3.0/-3.0 | +3.0/-2.0 | +2.0/-2.0 | +1.0/-1.0 | PLATED | NON-PLATED | QTY | 20 | 3826 | 38 | 6 | 62 | 2 | 4 | 1 | 11 | LAYER NAME | 0.0030 | 0.0044 | 0.0045 | FINISHED Cu | 1.47oz. | 0.5oz. | X-SECTION | DIELECTRIC THICKNESS | [INCHES] | L01 | L02 | L03 | L04 | L05 | L06 | L07 | L08 | L09 | L10 | L11 | L12 | PRIMARY SIDE | PRIMARY SIDE SILKSCREEN | PRIMARY SIDE SOLDERMASK | GROUND-PLANE-1 | INNER-SIGNAL-1 | GROUND-PLANE-2 | INNER-SIGNAL-2 | POWER-PLANE-1 | POWER-PLANE-2 | GROUND-PLANE-3 | INNER-SIGNAL-3 | GROUND-PLANE-4 | SECONDARY SIDE | SECONDARY SIDE SOLDERMASK | SECONDARY SIDE SILKSCREEN | SL# | 01 | 02 | 03 | 04 | 10 | 05 | 12 | 06 | 13 | 07 | 08 | 09 | STRIPLINE | MICROSTRIP | EDGE COUPLED STRIPLINE | EDGE COUPLED MICROSTRIP | TYPE | L3, L10 | L3, L5 | L5 | L3 | L1, L12 | LAYER | 5.5 | 3.5 | TRACEWIDTH(Mils) | 3 | 5 | 7.4 | SPACING(Mils) | NA | 4.3 | 4.4 | 6.5 | 100 | 90 | 133 | IMPEDANCE(Ohms) | 66 | 40 | 80 | 50 | REF LAYER | L4/L6 | L2/L4, L4/L6 | L2/L4, L9/L11 | L2/L4 | L2, L11 | L9/L11 | LAYER STACKUP | IMPEDANCE SPECIFICATIONS | PROC135E1 ASSEMBLY TOP (Variant 1) | PROC135E1 ASSEMBLY BOTTOM (Variant 1) | 6 - Provide serial numbers to the assembled boards for identification. | 7 - The assembled board are wrapped in ESD Covers(individual) and packed securely before shipment. | ASSEMBLY NOTES:- | 1 - All MSL components should be baked as per JEDEC standard. | 2 - PCB should be baked at 120 degree for 8 hours. | 3 - Board assembly must comply with workmanship standards IPC-A-610 Class 2, unless otherwise specified. | 4 - These assemblies are ESD sensitive, ESD precautions shall be observed. | 5 - These assemblies must be clean and free from flux and all contaminants. Use of no clean flux is not acceptable. | PROC101 E2 ASSEMBLY TOP | PROC101 E2 ASSEMBLY BOTTOM
